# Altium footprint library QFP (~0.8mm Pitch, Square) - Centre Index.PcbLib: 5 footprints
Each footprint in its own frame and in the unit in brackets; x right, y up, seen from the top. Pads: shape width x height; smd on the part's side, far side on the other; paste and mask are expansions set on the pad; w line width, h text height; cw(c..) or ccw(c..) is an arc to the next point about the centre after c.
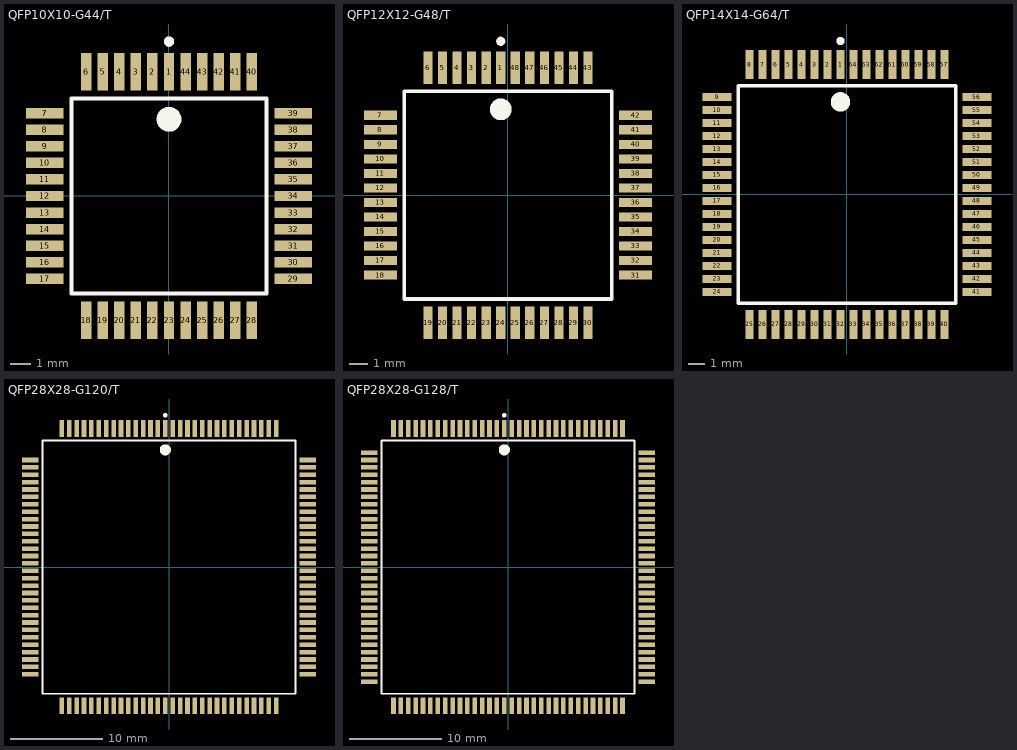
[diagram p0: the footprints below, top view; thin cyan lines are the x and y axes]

## QFP10X10-G44/T [mm]
pads (44):
  rect 0.5x1.8 smd: 1(0,6) 2(-0.8,6) 3(-1.6,6) 4(-2.4,6) 5(-3.2,6) 6(-4,6) 18(-4,-6) 19(-3.2,-6) 20(-2.4,-6) 21(-1.6,-6) 22(-0.8,-6) 23(0,-6) 24(0.8,-6) 25(1.6,-6) 26(2.4,-6) 27(3.2,-6) 28(4,-6) 40(4,6) 41(3.2,6) 42(2.4,6) 43(1.6,6) 44(0.8,6)
  rect 1.8x0.5 smd: 7(-6,4) 8(-6,3.2) 9(-6,2.4) 10(-6,1.6) 11(-6,0.8) 12(-6,0) 13(-6,-0.8) 14(-6,-1.6) 15(-6,-2.4) 16(-6,-3.2) 17(-6,-4) 29(6,-4) 30(6,-3.2) 31(6,-2.4) 32(6,-1.6) 33(6,-0.8) 34(6,0) 35(6,0.8) 36(6,1.6) 37(6,2.4) 38(6,3.2) 39(6,4)
Top Overlay:
  circle w0.25: c0,7.45 r0.125
  circle w0.6: c0,3.7 r0.3
  lines w0.2: -4.7,-4.7 4.7,-4.7 4.7,4.7 -4.7,4.7 -4.7,-4.7

## QFP12X12-G48/T [mm]
pads (48):
  rect 0.5x1.8 smd: 1(-0.4,7.025) 2(-1.2,7.025) 3(-2,7.025) 4(-2.8,7.025) 5(-3.6,7.025) 6(-4.4,7.025) 19(-4.4,-7.025) 20(-3.6,-7.025) 21(-2.8,-7.025) 22(-2,-7.025) 23(-1.2,-7.025) 24(-0.4,-7.025) 25(0.4,-7.025) 26(1.2,-7.025) 27(2,-7.025) 28(2.8,-7.025) 29(3.6,-7.025) 30(4.4,-7.025) 43(4.4,7.025) 44(3.6,7.025) 45(2.8,7.025) 46(2,7.025) 47(1.2,7.025) 48(0.4,7.025)
  rect 1.8x0.5 smd: 7(-7.025,4.4) 8(-7.025,3.6) 9(-7.025,2.8) 10(-7.025,2) 11(-7.025,1.2) 12(-7.025,0.4) 13(-7.025,-0.4) 14(-7.025,-1.2) 15(-7.025,-2) 16(-7.025,-2.8) 17(-7.025,-3.6) 18(-7.025,-4.4) 31(7.025,-4.4) 32(7.025,-3.6) 33(7.025,-2.8) 34(7.025,-2) 35(7.025,-1.2) 36(7.025,-0.4) 37(7.025,0.4) 38(7.025,1.2) 39(7.025,2) 40(7.025,2.8) 41(7.025,3.6) 42(7.025,4.4)
Top Overlay:
  circle w0.25: c-0.4,8.475 r0.125
  circle w0.6: c-0.4,4.725 r0.3
  lines w0.2: -5.725,-5.725 5.725,-5.725 5.725,5.725 -5.725,5.725 -5.725,-5.725

## QFP14X14-G64/T [mm]
pads (64):
  rect 0.5x1.8 smd: 1(-0.4,8) 2(-1.2,8) 3(-2,8) 4(-2.8,8) 5(-3.6,8) 6(-4.4,8) 7(-5.2,8) 8(-6,8) 25(-6,-8) 26(-5.2,-8) 27(-4.4,-8) 28(-3.6,-8) 29(-2.8,-8) 30(-2,-8) 31(-1.2,-8) 32(-0.4,-8) 33(0.4,-8) 34(1.2,-8) 35(2,-8) 36(2.8,-8) 37(3.6,-8) 38(4.4,-8) 39(5.2,-8) 40(6,-8) 57(6,8) 58(5.2,8) 59(4.4,8) 60(3.6,8) 61(2.8,8) 62(2,8) 63(1.2,8) 64(0.4,8)
  rect 1.8x0.5 smd: 9(-8,6) 10(-8,5.2) 11(-8,4.4) 12(-8,3.6) 13(-8,2.8) 14(-8,2) 15(-8,1.2) 16(-8,0.4) 17(-8,-0.4) 18(-8,-1.2) 19(-8,-2) 20(-8,-2.8) 21(-8,-3.6) 22(-8,-4.4) 23(-8,-5.2) 24(-8,-6) 41(8,-6) 42(8,-5.2) 43(8,-4.4) 44(8,-3.6) 45(8,-2.8) 46(8,-2) 47(8,-1.2) 48(8,-0.4) 49(8,0.4) 50(8,1.2) 51(8,2) 52(8,2.8) 53(8,3.6) 54(8,4.4) 55(8,5.2) 56(8,6)
Top Overlay:
  circle w0.6: c-0.4,5.7 r0.3
  circle w0.25: c-0.4,9.45 r0.125
  lines w0.2: -6.7,-6.7 -6.7,6.7 6.7,6.7 6.7,-6.7 -6.7,-6.7

## QFP28X28-G120/T [mm]
pads (120):
  rect 0.5x1.8 smd: 1(-0.4,15) 2(-1.2,15) 3(-2,15) 4(-2.8,15) 5(-3.6,15) 6(-4.4,15) 7(-5.2,15) 8(-6,15) 9(-6.8,15) 10(-7.6,15) 11(-8.4,15) 12(-9.2,15) 13(-10,15) 14(-10.8,15) 15(-11.6,15) 46(-11.6,-15) 47(-10.8,-15) 48(-10,-15) 49(-9.2,-15) 50(-8.4,-15) 51(-7.6,-15) 52(-6.8,-15) 53(-6,-15) 54(-5.2,-15) 55(-4.4,-15) 56(-3.6,-15) 57(-2.8,-15) 58(-2,-15) 59(-1.2,-15) 60(-0.4,-15) 61(0.4,-15) 62(1.2,-15) 63(2,-15) 64(2.8,-15) 65(3.6,-15) 66(4.4,-15) 67(5.2,-15) 68(6,-15) 69(6.8,-15) 70(7.6,-15) 71(8.4,-15) 72(9.2,-15) 73(10,-15) 74(10.8,-15) 75(11.6,-15) 106(11.6,15) 107(10.8,15) 108(10,15) 109(9.2,15) 110(8.4,15) 111(7.6,15) 112(6.8,15) 113(6,15) 114(5.2,15) 115(4.4,15) 116(3.6,15) 117(2.8,15) 118(2,15) 119(1.2,15) 120(0.4,15)
  rect 1.8x0.5 smd: 16(-15,11.6) 17(-15,10.8) 18(-15,10) 19(-15,9.2) 20(-15,8.4) 21(-15,7.6) 22(-15,6.8) 23(-15,6) 24(-15,5.2) 25(-15,4.4) 26(-15,3.6) 27(-15,2.8) 28(-15,2) 29(-15,1.2) 30(-15,0.4) 31(-15,-0.4) 32(-15,-1.2) 33(-15,-2) 34(-15,-2.8) 35(-15,-3.6) 36(-15,-4.4) 37(-15,-5.2) 38(-15,-6) 39(-15,-6.8) 40(-15,-7.6) 41(-15,-8.4) 42(-15,-9.2) 43(-15,-10) 44(-15,-10.8) 45(-15,-11.6) 76(15,-11.6) 77(15,-10.8) 78(15,-10) 79(15,-9.2) 80(15,-8.4) 81(15,-7.6) 82(15,-6.8) 83(15,-6) 84(15,-5.2) 85(15,-4.4) 86(15,-3.6) 87(15,-2.8) 88(15,-2) 89(15,-1.2) 90(15,-0.4) 91(15,0.4) 92(15,1.2) 93(15,2) 94(15,2.8) 95(15,3.6) 96(15,4.4) 97(15,5.2) 98(15,6) 99(15,6.8) 100(15,7.6) 101(15,8.4) 102(15,9.2) 103(15,10) 104(15,10.8) 105(15,11.6)
Top Overlay:
  circle w0.6: c-0.4,12.7 r0.3
  circle w0.25: c-0.4,16.45 r0.125
  lines w0.2: -13.7,-13.7 -13.7,13.7 13.7,13.7 13.7,-13.7 -13.7,-13.7

## QFP28X28-G128/T [mm]
pads (128):
  rect 0.5x1.8 smd: 1(-0.4,15) 2(-1.2,15) 3(-2,15) 4(-2.8,15) 5(-3.6,15) 6(-4.4,15) 7(-5.2,15) 8(-6,15) 9(-6.8,15) 10(-7.6,15) 11(-8.4,15) 12(-9.2,15) 13(-10,15) 14(-10.8,15) 15(-11.6,15) 16(-12.4,15) 49(-12.4,-15) 50(-11.6,-15) 51(-10.8,-15) 52(-10,-15) 53(-9.2,-15) 54(-8.4,-15) 55(-7.6,-15) 56(-6.8,-15) 57(-6,-15) 58(-5.2,-15) 59(-4.4,-15) 60(-3.6,-15) 61(-2.8,-15) 62(-2,-15) 63(-1.2,-15) 64(-0.4,-15) 65(0.4,-15) 66(1.2,-15) 67(2,-15) 68(2.8,-15) 69(3.6,-15) 70(4.4,-15) 71(5.2,-15) 72(6,-15) 73(6.8,-15) 74(7.6,-15) 75(8.4,-15) 76(9.2,-15) 77(10,-15) 78(10.8,-15) 79(11.6,-15) 80(12.4,-15) 113(12.4,15) 114(11.6,15) 115(10.8,15) 116(10,15) 117(9.2,15) 118(8.4,15) 119(7.6,15) 120(6.8,15) 121(6,15) 122(5.2,15) 123(4.4,15) 124(3.6,15) 125(2.8,15) 126(2,15) 127(1.2,15) 128(0.4,15)
  rect 1.8x0.5 smd: 17(-15,12.4) 18(-15,11.6) 19(-15,10.8) 20(-15,10) 21(-15,9.2) 22(-15,8.4) 23(-15,7.6) 24(-15,6.8) 25(-15,6) 26(-15,5.2) 27(-15,4.4) 28(-15,3.6) 29(-15,2.8) 30(-15,2) 31(-15,1.2) 32(-15,0.4) 33(-15,-0.4) 34(-15,-1.2) 35(-15,-2) 36(-15,-2.8) 37(-15,-3.6) 38(-15,-4.4) 39(-15,-5.2) 40(-15,-6) 41(-15,-6.8) 42(-15,-7.6) 43(-15,-8.4) 44(-15,-9.2) 45(-15,-10) 46(-15,-10.8) 47(-15,-11.6) 48(-15,-12.4) 81(15,-12.4) 82(15,-11.6) 83(15,-10.8) 84(15,-10) 85(15,-9.2) 86(15,-8.4) 87(15,-7.6) 88(15,-6.8) 89(15,-6) 90(15,-5.2) 91(15,-4.4) 92(15,-3.6) 93(15,-2.8) 94(15,-2) 95(15,-1.2) 96(15,-0.4) 97(15,0.4) 98(15,1.2) 99(15,2) 100(15,2.8) 101(15,3.6) 102(15,4.4) 103(15,5.2) 104(15,6) 105(15,6.8) 106(15,7.6) 107(15,8.4) 108(15,9.2) 109(15,10) 110(15,10.8) 111(15,11.6) 112(15,12.4)
Top Overlay:
  circle w0.25: c-0.4,16.45 r0.125
  circle w0.6: c-0.4,12.7 r0.3
  lines w0.2: -13.7,-13.7 13.7,-13.7 13.7,13.7 -13.7,13.7 -13.7,-13.7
